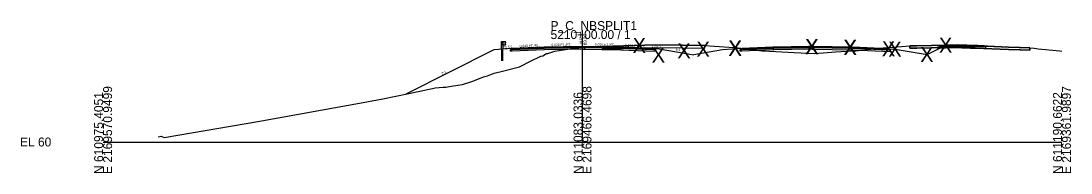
# Model space of a CAD drawing. Extents: x -26 to 1303, y -3010 to 12038.
# Drawn here: x 974.3 to 1302.8, y 5990.3 to 6037.8 of the extents above; entities that cross this region are included whole.
import ezdxf

# ---------------------------------------------------------------- set-up
doc = ezdxf.new("R2010")
doc.units = 0
for name, color, linetype in [('RD_GPK_XS_Cell', 7, 'Continuous'), ('RD_GPK_XS_Text_Node', 7, 'Continuous'), ('RD_PD_Final_TrvlWay', 7, 'Continuous'), ('RD_XS_Base', 7, 'Continuous'), ('RD_XS_ExGround', 7, 'Continuous'), ('RD_XS_ExPaveRet', 7, 'Continuous'), ('RD_XS_GR', 7, 'Continuous'), ('RD_XS_Greenside', 7, 'Continuous'), ('RD_XS_Pave', 7, 'Continuous'), ('RD_XS_PaveOvlay_CP', 7, 'Continuous'), ('RD_XS_TieSlope', 7, 'Continuous'), ('RD_XS_TX_Elev_EX', 7, 'Continuous'), ('RD_XS_TX_Elev_PR', 7, 'Continuous'), ('RD_XS_TX_ShdSlope', 7, 'Continuous'), ('RD_XS_TX_Slope', 7, 'Continuous')]:
    doc.layers.add(name, color=color, linetype=linetype)

msp = doc.modelspace()

# ---------------------------------------------------------------- linework, layer by layer
at = {"layer": 'RD_GPK_XS_Cell'}
for p, q in [((1150, 6000), (1150, 6035)), ((1000, 6000), (1150, 6000)), ((1150, 6000), (1300, 6000))]:
    msp.add_line(p, q, dxfattribs=at)
at = {"layer": 'RD_PD_Final_TrvlWay'}
for p, q in [((1125.11, 6029.02), (1124.61, 6028.98)), ((1124.61, 6028.98), (1124.61, 6025.42)), ((1125.11, 6025.42), (1125.11, 6029.02))]:
    msp.add_line(p, q, dxfattribs=at)
at = {"layer": 'RD_XS_Base'}
for p, q in [((1127.5, 6028.92), (1128, 6028.94)), ((1127.5, 6028.42), (1127.5, 6028.92)), ((1127.5, 6028.92), (1127.5, 6028.92)), ((1128, 6028.94), (1138, 6029.34)), ((1128, 6028.94), (1128, 6028.94)), ((1138, 6028.84), (1128, 6028.44)), ((1138, 6029.34), (1150, 6029.58)), ((1138, 6029.34), (1138, 6029.34)), ((1150, 6029.08), (1138, 6028.84)), ((1138, 6028.84), (1138, 6028.84)), ((1150, 6029.58), (1150, 6029.74)), ((1150, 6029.74), (1150, 6029.08)), ((1150, 6029.58), (1150, 6029.08)), ((1162, 6029.34), (1150, 6029.58)), ((1150, 6029.58), (1150, 6029.58)), ((1150, 6029.08), (1150, 6029.08)), ((1150, 6029.08), (1150, 6029.08)), ((1150, 6029.08), (1162, 6028.84)), ((1172, 6028.94), (1162, 6029.34)), ((1162, 6028.84), (1172.5, 6028.42)), ((1164, 6029.26), (1164, 6029.26)), ((1164, 6028.76), (1164, 6028.76)), ((1172.5, 6028.92), (1172, 6028.94)), ((1172, 6028.94), (1172, 6028.94)), ((1172.5, 6028.42), (1172.5, 6028.92)), ((1172.5, 6028.92), (1172.5, 6028.92)), ((1199.32, 6028.92), (1199.81, 6028.94)), ((1199.32, 6028.91), (1199.32, 6028.92)), ((1199.32, 6028.42), (1199.32, 6028.91)), ((1199.81, 6028.94), (1199.82, 6028.94)), ((1199.82, 6028.94), (1209.52, 6029.33)), ((1209.52, 6028.83), (1199.82, 6028.44)), ((1209.52, 6029.33), (1209.82, 6029.34)), ((1209.82, 6028.84), (1209.52, 6028.83)), ((1209.82, 6029.34), (1220.74, 6029.56)), ((1220.74, 6029.06), (1209.82, 6028.84)), ((1220.74, 6029.56), (1221.82, 6029.58)), ((1221.82, 6029.08), (1220.74, 6029.06)), ((1221.82, 6029.73), (1221.82, 6029.74)), ((1221.82, 6029.74), (1221.82, 6029.71)), ((1221.82, 6029.58), (1221.82, 6029.73)), ((1221.82, 6029.71), (1221.82, 6029.08)), ((1221.82, 6029.58), (1221.82, 6029.56)), ((1221.82, 6029.58), (1221.82, 6029.58)), ((1222.37, 6029.57), (1221.82, 6029.58)), ((1221.82, 6029.58), (1221.82, 6029.58)), ((1221.82, 6029.56), (1221.82, 6029.08)), ((1221.82, 6029.08), (1222.37, 6029.07)), ((1233.82, 6029.34), (1222.37, 6029.57)), ((1222.37, 6029.07), (1233.82, 6028.84)), ((1234.46, 6029.31), (1233.82, 6029.34)), ((1233.82, 6028.84), (1234.49, 6028.81)), ((1245.82, 6028.86), (1234.46, 6029.31)), ((1234.49, 6028.81), (1246.32, 6028.34)), ((1245.85, 6028.86), (1245.82, 6028.86)), ((1246.32, 6028.84), (1245.85, 6028.86)), ((1246.32, 6028.81), (1246.32, 6028.84)), ((1246.32, 6028.34), (1246.32, 6028.81)), ((1261.19, 6029.77), (1261.69, 6029.78)), ((1261.19, 6029.27), (1261.19, 6029.77)), ((1261.69, 6029.28), (1261.19, 6029.27)), ((1261.69, 6029.78), (1263.69, 6029.82)), ((1263.69, 6029.32), (1261.69, 6029.28)), ((1263.69, 6029.82), (1268.69, 6029.92)), ((1268.69, 6029.42), (1263.69, 6029.32)), ((1268.69, 6030), (1268.69, 6030.08)), ((1268.69, 6030.08), (1268.69, 6029.77)), ((1268.69, 6029.92), (1268.69, 6030)), ((1271.42, 6029.86), (1268.69, 6029.92)), ((1268.69, 6029.92), (1268.69, 6029.42)), ((1268.69, 6029.77), (1268.69, 6029.42)), ((1268.69, 6029.42), (1271.42, 6029.36)), ((1273.69, 6029.82), (1271.42, 6029.86)), ((1271.42, 6029.36), (1273.69, 6029.32)), ((1274.58, 6029.8), (1273.69, 6029.82)), ((1273.69, 6029.32), (1274.81, 6029.3)), ((1275.69, 6029.78), (1274.58, 6029.8)), ((1274.81, 6029.3), (1276.19, 6029.27)), ((1275.91, 6029.77), (1275.69, 6029.78)), ((1276.19, 6029.77), (1275.91, 6029.77)), ((1276.19, 6029.49), (1276.19, 6029.77)), ((1276.19, 6029.27), (1276.19, 6029.49)), ((1128, 6028.44), (1127.5, 6028.42)), ((1127.5, 6028.42), (1127.5, 6028.42)), ((1127.5, 6028.42), (1127.5, 6028.42)), ((1128, 6028.44), (1128, 6028.44)), ((1172.5, 6028.42), (1172.5, 6028.42)), ((1172.5, 6028.42), (1172.5, 6028.42)), ((1199.81, 6028.44), (1199.32, 6028.42)), ((1199.82, 6028.44), (1199.81, 6028.44))]:
    msp.add_line(p, q, dxfattribs=at)
at = {"layer": 'RD_XS_ExGround'}
msp.add_lwpolyline([(1017.27, 6001.58), (1018.19, 6001.84), (1019.14, 6001.4), (1048.4, 6006.42), (1081.41, 6012.38), (1087.49, 6013.47), (1095.69, 6015.22), (1102.02, 6016.56), (1103.11, 6016.74), (1103.93, 6016.93), (1106.42, 6017.19), (1107.19, 6017.19), (1108.88, 6017.46), (1112.42, 6018.01), (1115.68, 6018.98), (1119.06, 6020.38), (1120.3, 6020.65), (1122.38, 6021.5), (1124.96, 6022.12), (1130.26, 6023.46), (1130.69, 6023.7), (1133.49, 6025.2), (1136.96, 6026.8), (1137.58, 6026.94), (1138.7, 6027.65), (1139.14, 6027.7), (1141.29, 6028.45), (1145.44, 6028.99), (1150.63, 6029.65), (1156.16, 6029.82), (1172.88, 6030.35), (1181.31, 6030.24), (1188.24, 6030.14), (1197.33, 6029.54), (1197.85, 6029.51), (1197.9, 6029.51), (1206.26, 6028.51), (1206.35, 6028.5), (1206.37, 6028.5), (1206.41, 6028.5), (1206.64, 6028.49), (1216.21, 6027.99), (1222.67, 6027.71), (1229.12, 6028.16), (1232.7, 6028.45), (1235.17, 6028.51), (1235.24, 6028.51), (1235.37, 6028.52), (1244.05, 6029.5), (1247.21, 6029.71), (1252.38, 6030.08), (1263.8, 6030.29), (1267.33, 6030.36), (1283.32, 6029.71), (1289.91, 6029.46), (1291.34, 6029.3), (1292.57, 6029.18), (1299.32, 6028.5), (1300, 6028.4)], dxfattribs=at)
at = {"layer": 'RD_XS_ExPaveRet'}
for p, q in [((1156.16, 6029.82), (1150.63, 6029.65)), ((1172.88, 6030.35), (1156.16, 6029.82)), ((1181.31, 6030.24), (1172.88, 6030.35)), ((1188.24, 6030.14), (1181.31, 6030.24)), ((1254.65, 6030.12), (1252.38, 6030.08)), ((1263.8, 6030.29), (1254.65, 6030.12)), ((1265.21, 6030.32), (1263.8, 6030.29)), ((1267.33, 6030.36), (1265.21, 6030.32))]:
    msp.add_line(p, q, dxfattribs=at)
for points in [[(1181.31, 6030.24), (1172.88, 6030.35), (1172.88, 6030.35), (1156.16, 6029.82), (1156.16, 6029.82), (1150.63, 6029.65), (1150.63, 6029.65), (1150.63, 6028.9), (1150.63, 6028.9), (1150.63, 6028.9), (1156.16, 6029.07), (1156.16, 6029.07), (1172.88, 6029.6), (1172.88, 6029.6), (1181.31, 6029.49), (1181.31, 6029.49), (1188.24, 6029.39), (1188.24, 6029.39), (1188.24, 6030.14), (1181.31, 6030.24), (1181.31, 6030.24)], [(1150.63, 6029.65), (1150.63, 6028.9), (1156.16, 6029.07), (1172.88, 6029.6), (1181.31, 6029.49), (1188.24, 6029.39), (1188.24, 6030.14)], [(1289.91, 6029.46), (1289.91, 6029.46), (1289.91, 6029.22), (1289.91, 6028.71), (1289.91, 6028.71), (1289.91, 6028.71), (1286.95, 6028.82), (1283.32, 6028.96), (1270.27, 6029.49), (1267.33, 6029.61), (1265.21, 6029.57), (1263.8, 6029.54), (1254.65, 6029.37), (1252.38, 6029.33), (1252.38, 6029.51), (1252.38, 6030.08), (1254.65, 6030.12), (1263.8, 6030.29), (1265.21, 6030.32), (1267.33, 6030.36), (1270.27, 6030.24), (1283.32, 6029.71), (1286.95, 6029.57), (1289.91, 6029.46), (1289.91, 6029.46)], [(1252.38, 6030.08), (1252.38, 6029.51), (1252.38, 6029.33), (1254.65, 6029.37), (1263.8, 6029.54), (1265.21, 6029.57), (1267.33, 6029.61), (1270.27, 6029.49), (1283.32, 6028.96), (1286.95, 6028.82), (1289.91, 6028.71), (1289.91, 6028.71), (1289.91, 6028.71), (1289.91, 6029.22), (1289.91, 6029.46), (1289.91, 6029.46), (1289.91, 6029.46)], [(1283.32, 6029.71), (1270.27, 6030.24), (1267.33, 6030.36)], [(1289.91, 6029.46), (1286.95, 6029.57), (1283.32, 6029.71)]]:
    msp.add_lwpolyline(points, dxfattribs=at)
at = {"layer": 'RD_XS_GR'}
for points in [[(1125.11, 6031.42), (1125.11, 6029.02), (1124.61, 6028.98), (1124.61, 6031.42), (1124.86, 6031.42), (1125.11, 6031.42)], [(1125.77, 6031.42), (1125.77, 6030.25), (1125.11, 6030.25), (1125.11, 6031.42), (1125.77, 6031.42)], [(1126.04, 6031.13), (1125.77, 6031.42), (1125.77, 6030.25), (1125.77, 6030.25), (1125.77, 6030.25), (1126.04, 6030.54), (1126.04, 6030.54), (1125.77, 6030.84), (1125.77, 6030.84), (1126.04, 6031.13), (1126.04, 6031.13)]]:
    msp.add_lwpolyline(points, dxfattribs=at)
at = {"layer": 'RD_XS_Greenside'}
for p, q in [((1122.29, 6028.8), (1094.71, 6015.01)), ((1174, 6029.1), (1184.86, 6027.29)), ((1193.82, 6028.78), (1184.86, 6027.29)), ((1247.82, 6029.02), (1257.82, 6027.35)), ((1257.82, 6027.35), (1263.69, 6030.29))]:
    msp.add_line(p, q, dxfattribs=at)
at = {"layer": 'RD_XS_Pave'}
for p, q in [((1138, 6029.66), (1128, 6029.26)), ((1138, 6029.5), (1128, 6029.1)), ((1128, 6029.1), (1138, 6029.5)), ((1128, 6028.94), (1138, 6029.34)), ((1128, 6029.26), (1128, 6029.26)), ((1128, 6029.26), (1128, 6029.1)), ((1128, 6029.1), (1128, 6029.1)), ((1128, 6029.1), (1128, 6028.94)), ((1128, 6029.1), (1128, 6029.1)), ((1128, 6029.1), (1128, 6029.1)), ((1128, 6028.94), (1128, 6028.94)), ((1128, 6028.94), (1128, 6028.94)), ((1150, 6029.9), (1138, 6029.66)), ((1150, 6029.74), (1138, 6029.5)), ((1138, 6029.5), (1150, 6029.74)), ((1138, 6029.66), (1138, 6029.66)), ((1138, 6029.34), (1150, 6029.58)), ((1138, 6029.5), (1138, 6029.5)), ((1138, 6029.5), (1138, 6029.5)), ((1138, 6029.34), (1138, 6029.34)), ((1162, 6029.66), (1150, 6029.9)), ((1150, 6029.58), (1150, 6029.74)), ((1150, 6029.74), (1162, 6029.5)), ((1162, 6029.5), (1150, 6029.74)), ((1150, 6029.74), (1150, 6029.58)), ((1150, 6029.58), (1150, 6029.58)), ((1150, 6029.58), (1150, 6029.58)), ((1150, 6029.58), (1162, 6029.34)), ((1172, 6029.26), (1162, 6029.66)), ((1162, 6029.5), (1172, 6029.1)), ((1172, 6029.1), (1162, 6029.5)), ((1162, 6029.34), (1172, 6028.94)), ((1164, 6029.58), (1164, 6029.58)), ((1164, 6029.42), (1164, 6029.42)), ((1164, 6029.42), (1164, 6029.42)), ((1164, 6029.26), (1164, 6029.26)), ((1172, 6029.1), (1172, 6029.26)), ((1172, 6029.26), (1172, 6029.26)), ((1172, 6029.1), (1172, 6029.1)), ((1172, 6029.1), (1172, 6029.1)), ((1172, 6028.94), (1172, 6029.1)), ((1172, 6029.1), (1172, 6029.1)), ((1172, 6028.94), (1172, 6028.94)), ((1172, 6028.94), (1172, 6028.94)), ((1209.52, 6029.65), (1199.82, 6029.26)), ((1209.52, 6029.49), (1199.82, 6029.1)), ((1199.82, 6029.1), (1209.52, 6029.49)), ((1199.82, 6028.94), (1209.52, 6029.33)), ((1199.82, 6029.26), (1199.82, 6029.25)), ((1199.82, 6029.25), (1199.82, 6029.1)), ((1199.82, 6029.1), (1199.82, 6029.09)), ((1199.82, 6029.09), (1199.82, 6028.94)), ((1209.82, 6029.66), (1209.52, 6029.65)), ((1209.82, 6029.5), (1209.52, 6029.49)), ((1209.52, 6029.49), (1209.82, 6029.5)), ((1209.52, 6029.33), (1209.82, 6029.34)), ((1220.74, 6029.88), (1209.82, 6029.66)), ((1220.74, 6029.72), (1209.82, 6029.5)), ((1209.82, 6029.5), (1220.74, 6029.72)), ((1209.82, 6029.34), (1220.74, 6029.56)), ((1221.82, 6029.9), (1220.74, 6029.88)), ((1221.82, 6029.74), (1220.74, 6029.72)), ((1220.74, 6029.72), (1221.82, 6029.74)), ((1220.74, 6029.56), (1221.82, 6029.58)), ((1222.37, 6029.89), (1221.82, 6029.9)), ((1221.82, 6029.73), (1221.82, 6029.74)), ((1221.82, 6029.74), (1222.37, 6029.73)), ((1222.37, 6029.73), (1221.82, 6029.74)), ((1221.82, 6029.74), (1221.82, 6029.74)), ((1221.82, 6029.74), (1221.82, 6029.74)), ((1221.82, 6029.74), (1221.82, 6029.73)), ((1221.82, 6029.58), (1221.82, 6029.73)), ((1221.82, 6029.73), (1221.82, 6029.58)), ((1221.82, 6029.58), (1221.82, 6029.58)), ((1221.82, 6029.58), (1221.82, 6029.58)), ((1221.82, 6029.58), (1222.37, 6029.57)), ((1233.82, 6029.66), (1222.37, 6029.89)), ((1222.37, 6029.73), (1233.82, 6029.5)), ((1233.82, 6029.5), (1222.37, 6029.73)), ((1222.37, 6029.57), (1233.82, 6029.34)), ((1234.46, 6029.63), (1233.82, 6029.66)), ((1233.82, 6029.5), (1234.46, 6029.47)), ((1234.46, 6029.47), (1233.82, 6029.5)), ((1233.82, 6029.34), (1234.46, 6029.31)), ((1245.82, 6029.18), (1234.46, 6029.63)), ((1234.46, 6029.47), (1245.82, 6029.02)), ((1245.82, 6029.02), (1234.46, 6029.47)), ((1234.46, 6029.31), (1245.82, 6028.86)), ((1245.82, 6029.17), (1245.82, 6029.18)), ((1245.82, 6029.02), (1245.82, 6029.17)), ((1245.82, 6029.01), (1245.82, 6029.02)), ((1245.82, 6028.86), (1245.82, 6029.01)), ((1262.64, 6030.12), (1261.69, 6030.1)), ((1261.69, 6030.1), (1261.69, 6030.02)), ((1261.69, 6030.02), (1261.69, 6029.94)), ((1263.69, 6029.98), (1261.69, 6029.94)), ((1261.69, 6029.94), (1262.64, 6029.96)), ((1261.69, 6029.94), (1261.69, 6029.78)), ((1261.69, 6029.78), (1263.69, 6029.82)), ((1263.69, 6030.14), (1262.64, 6030.12)), ((1262.64, 6029.96), (1263.69, 6029.98)), ((1266.36, 6030.19), (1263.69, 6030.14)), ((1268.69, 6030.08), (1263.69, 6029.98)), ((1263.69, 6029.98), (1266.36, 6030.03)), ((1263.69, 6029.82), (1268.69, 6029.92)), ((1268.69, 6030.24), (1266.36, 6030.19)), ((1266.36, 6030.03), (1268.69, 6030.08)), ((1271.42, 6030.18), (1268.69, 6030.24)), ((1268.69, 6030.08), (1271.42, 6030.02)), ((1273.69, 6029.98), (1268.69, 6030.08)), ((1268.69, 6030.08), (1268.69, 6029.92)), ((1268.69, 6029.92), (1268.69, 6030.08)), ((1268.69, 6029.92), (1273.69, 6029.82)), ((1273.69, 6030.14), (1271.42, 6030.18)), ((1271.42, 6030.02), (1273.69, 6029.98)), ((1274.58, 6030.12), (1273.69, 6030.14)), ((1273.69, 6029.98), (1274.58, 6029.96)), ((1275.69, 6029.94), (1273.69, 6029.98)), ((1273.69, 6029.82), (1275.69, 6029.78)), ((1275.69, 6030.1), (1274.58, 6030.12)), ((1274.58, 6029.96), (1275.69, 6029.94)), ((1275.69, 6030.03), (1275.69, 6030.1)), ((1275.69, 6029.94), (1275.69, 6030.03)), ((1275.69, 6029.78), (1275.69, 6029.94))]:
    msp.add_line(p, q, dxfattribs=at)
at = {"layer": 'RD_XS_PaveOvlay_CP'}
for p, q in [((1128, 6029.26), (1138, 6029.66)), ((1138, 6029.66), (1150, 6029.9)), ((1150, 6029.9), (1162, 6029.66)), ((1162, 6029.66), (1172, 6029.26)), ((1209.52, 6029.65), (1199.82, 6029.26)), ((1209.82, 6029.66), (1209.52, 6029.65)), ((1220.74, 6029.88), (1209.82, 6029.66)), ((1221.82, 6029.9), (1220.74, 6029.88)), ((1222.37, 6029.89), (1221.82, 6029.9)), ((1233.82, 6029.66), (1222.37, 6029.89)), ((1234.46, 6029.63), (1233.82, 6029.66)), ((1245.82, 6029.18), (1234.46, 6029.63)), ((1261.69, 6030.1), (1263.69, 6030.14)), ((1263.69, 6030.14), (1268.69, 6030.24)), ((1268.69, 6030.24), (1273.69, 6030.14)), ((1273.69, 6030.14), (1275.69, 6030.1))]:
    msp.add_line(p, q, dxfattribs=at)
at = {"layer": 'RD_XS_TieSlope'}
for p, q in [((1128, 6029.26), (1122.29, 6028.8)), ((1172, 6029.26), (1174, 6029.1)), ((1199.82, 6029.26), (1193.82, 6028.78)), ((1245.82, 6029.18), (1247.82, 6029.02))]:
    msp.add_line(p, q, dxfattribs=at)

# ---------------------------------------------------------------- texts
at = {"layer": 'RD_GPK_XS_Cell'}
for s, p in [('5210+00.00 / 1', (1140, 6032.2)), ('P_C_NBSPLIT1', (1140, 6035)), ('EL 60', (974, 5998.6))]:
    msp.add_text(s, height=2.8, dxfattribs=at).set_placement(p)
for s, p in [('E 2169570.9499', (1002.8, 5990)), ('N 611083.0336', (1150, 5990)), ('E 2169466.4698', (1152.8, 5990)), ('E 2169361.9897', (1302.8, 5990)), ('N 610975.4051', (1000, 5990)), ('N 611190.6622', (1300, 5990))]:
    msp.add_text(s, height=2.8, rotation=90, dxfattribs=at).set_placement(p)
at = {"layer": 'RD_GPK_XS_Text_Node'}
for p in [(1165.68, 6027.85), (1219.66, 6027.55), (1219.66, 6027.4), (1231.66, 6027.31), (1261.52, 6027.94), (1171.66, 6024.86), (1179.66, 6026.19), (1185.66, 6026.67), (1195.66, 6027.07), (1195.66, 6026.91), (1231.66, 6027.16), (1243.66, 6026.83), (1245.66, 6026.68), (1255.66, 6025.01)]:
    msp.add_text('X', height=4.69, dxfattribs=at).set_placement(p)
at = {"layer": 'RD_XS_TX_Elev_EX'}
msp.add_text('89.57', height=0.6, rotation=90, dxfattribs=at).set_placement((1149.73, 6030.7))
at = {"layer": 'RD_XS_TX_Elev_PR'}
msp.add_text('89.90', height=1, rotation=90, dxfattribs=at).set_placement((1151.3, 6030.29))
at = {"layer": 'RD_XS_TX_ShdSlope'}
for rotation, p in [(4.5739, (1125.26, 6029.23)), (355.4261, (1171.67, 6029.61))]:
    msp.add_text('12.5:1', height=0.75, rotation=rotation, dxfattribs=at).set_placement(p)
at = {"layer": 'RD_XS_TX_Slope'}
for s, rotation, p in [('0.040 FT./FT.', 2.2906, (1130.34, 6029.61)), ('0.020 FT./FT.', 1.1458, (1140.25, 6029.96)), ('0.020 FT./FT.', 358.8542, (1153.85, 6030.11)), ('0.040 FT./FT.', 357.7094, (1163.26, 6029.86)), ('6:1', 350.5377, (1179.13, 6028.67)), ('2:1', 26.5651, (1106.13, 6021.06))]:
    msp.add_text(s, height=0.75, rotation=rotation, dxfattribs=at).set_placement(p)

doc.saveas('drawing.dxf')
